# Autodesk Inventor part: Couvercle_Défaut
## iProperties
Shininess: 64.0
Length Units: 11269
Angle Units: 11279
Time Units: 11290
Mass Units: 11283
Length Display Precision: 3
Angle Display Precision: 2
Compacted: True
Part Number: Couvercle_Défaut
Document SubType Name: Modeling
Created: 2006-01
Material: Par défaut
Designer: Fricot
Density: 0.0
Volumn: 0.0
Area: 0.0
PropertySet Name: Model Information
Control State: 0
Master: False
Checked Out: False
Author: Fricot
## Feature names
1. Base1
